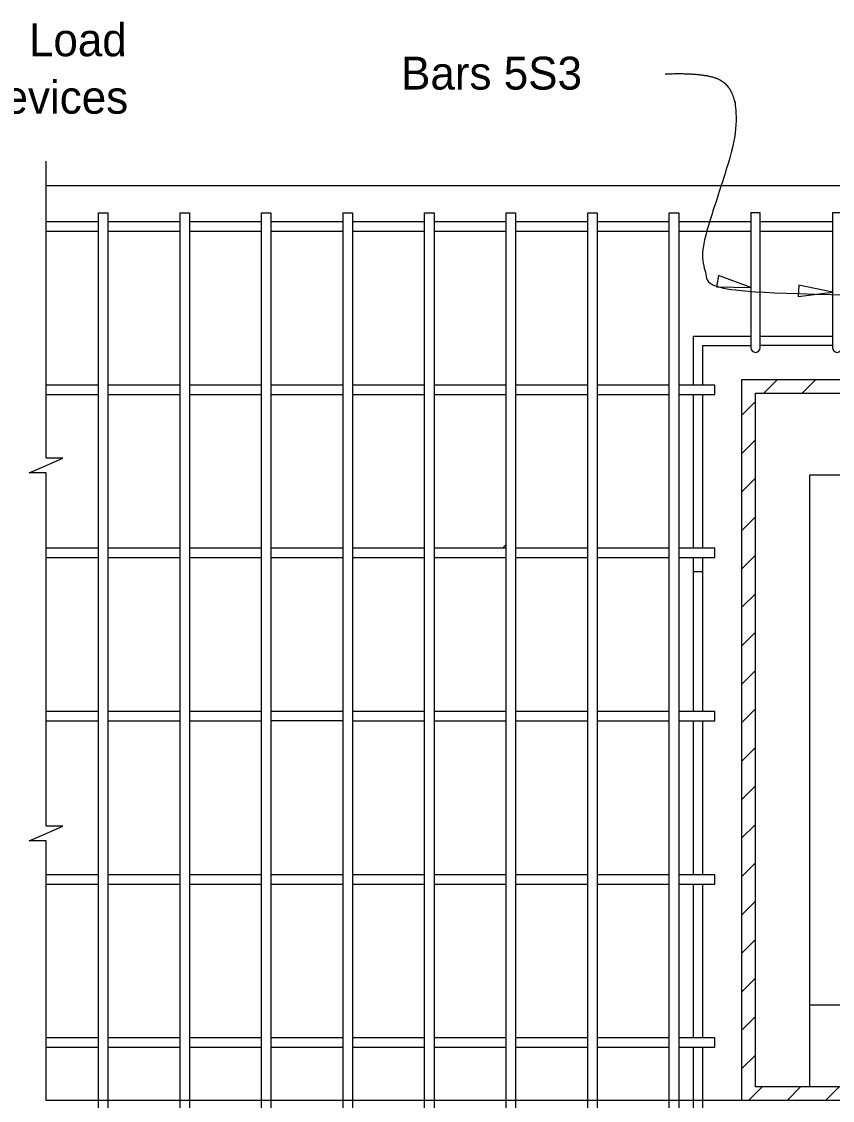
# Model space of a CAD drawing. Extents: x 120577.8 to 120649.9, y 120677.2 to 120721.6.
# Drawn here: x 120598.08 to 120603.05, y 120708.42 to 120715.03 of the extents above; entities that cross this region are included whole.
import ezdxf

# ---------------------------------------------------------------- set-up
doc = ezdxf.new("R2010")
doc.units = 0
for name, color, linetype in [('AdhocPoint_dp', 7, 'Continuous'), ('Border', 7, 'Continuous'), ('Patterning', 7, 'Continuous'), ('PlotBorder_dp', 7, 'Continuous'), ('TextMisc', 7, 'Continuous')]:
    doc.layers.add(name, color=color, linetype=linetype)

msp = doc.modelspace()

# ---------------------------------------------------------------- linework, layer by layer
at = {"layer": 'Border'}
for p, q in [((120602.6314, 120712.7572), (120602.7147, 120712.8405)), ((120602.867, 120712.7572), (120602.9503, 120712.8405)), ((120602.5808, 120708.5072), (120602.5808, 120712.7572)), ((120602.5808, 120712.7572), (120607.5808, 120712.7572)), ((120602.4975, 120712.6232), (120602.5808, 120712.7065)), ((120602.4975, 120712.3877), (120602.5808, 120712.471)), ((120602.4975, 120712.1521), (120602.5808, 120712.2354)), ((120602.9141, 120712.2572), (120607.2474, 120712.2572)), ((120602.9141, 120708.5072), (120602.9141, 120712.2572)), ((120602.4975, 120711.9166), (120602.5808, 120711.9999)), ((120602.4975, 120711.681), (120602.5808, 120711.7643)), ((120602.4975, 120711.4454), (120602.5808, 120711.5287)), ((120602.4975, 120711.2099), (120602.5808, 120711.2932)), ((120602.4975, 120710.9743), (120602.5808, 120711.0576)), ((120602.4975, 120710.7388), (120602.5808, 120710.8221)), ((120602.4975, 120710.5032), (120602.5808, 120710.5865)), ((120602.4975, 120710.2677), (120602.5808, 120710.351)), ((120602.4975, 120710.0321), (120602.5808, 120710.1154)), ((120602.4975, 120709.7966), (120602.5808, 120709.8799)), ((120602.4975, 120709.561), (120602.5808, 120709.6443)), ((120602.4975, 120709.3255), (120602.5808, 120709.4088)), ((120602.4975, 120709.0899), (120602.5808, 120709.1732)), ((120607.2474, 120709.0072), (120602.9141, 120709.0072)), ((120602.4975, 120708.8543), (120602.5808, 120708.9376)), ((120602.4975, 120708.6188), (120602.5808, 120708.7021)), ((120602.5381, 120708.4239), (120602.6214, 120708.5072)), ((120607.5808, 120708.5072), (120602.5808, 120708.5072)), ((120602.7736, 120708.4239), (120602.8569, 120708.5072)), ((120603.0092, 120708.4239), (120603.0925, 120708.5072))]:
    msp.add_line(p, q, dxfattribs=at)
at = {"layer": 'Patterning'}
for p, q in [((120598.5521, 120707.2437), (120598.5521, 120713.8614)), ((120598.5521, 120713.8614), (120598.6094, 120713.8614)), ((120598.6094, 120713.8614), (120598.6094, 120707.9744)), ((120599.0521, 120707.2437), (120599.0521, 120713.8614)), ((120599.0521, 120713.8614), (120599.1094, 120713.8614)), ((120599.1094, 120713.8614), (120599.1094, 120707.9744)), ((120599.5521, 120707.2437), (120599.5521, 120713.8614)), ((120599.5521, 120713.8614), (120599.6094, 120713.8614)), ((120599.6094, 120713.8614), (120599.6094, 120707.9744)), ((120600.0521, 120707.2437), (120600.0521, 120713.8614)), ((120600.0521, 120713.8614), (120600.1094, 120713.8614)), ((120600.1094, 120713.8614), (120600.1094, 120707.9744)), ((120600.5521, 120707.2437), (120600.5521, 120713.8614)), ((120600.5521, 120713.8614), (120600.6094, 120713.8614)), ((120600.6094, 120713.8614), (120600.6094, 120707.9744)), ((120601.0521, 120707.2437), (120601.0521, 120713.8614)), ((120601.0521, 120713.8614), (120601.1094, 120713.8614)), ((120601.1094, 120713.8614), (120601.1094, 120707.9744)), ((120601.5521, 120707.2437), (120601.5521, 120713.8614)), ((120601.5521, 120713.8614), (120601.6094, 120713.8614)), ((120601.6094, 120713.8614), (120601.6094, 120707.9744)), ((120602.0521, 120707.2437), (120602.0521, 120713.8614)), ((120602.0521, 120713.8614), (120602.1094, 120713.8614)), ((120602.1094, 120713.8614), (120602.1094, 120707.9744)), ((120602.6094, 120713.8614), (120602.5521, 120713.8614)), ((120602.5521, 120713.8614), (120602.5521, 120713.0358)), ((120602.6094, 120713.0358), (120602.6094, 120713.8614)), ((120603.1094, 120713.8614), (120603.0521, 120713.8614)), ((120603.0521, 120713.8614), (120603.0521, 120713.0358)), ((120602.1974, 120713.1061), (120602.1974, 120712.8067)), ((120602.2547, 120713.0488), (120602.5521, 120713.0488)), ((120602.2547, 120713.0488), (120602.2547, 120712.8067)), ((120602.3308, 120712.7494), (120602.3308, 120712.8067)), ((120602.1974, 120712.7494), (120602.1974, 120711.8067)), ((120602.2547, 120712.7494), (120602.2547, 120711.8067)), ((120601.029, 120711.8067), (120601.0521, 120711.8298)), ((120602.3308, 120711.7494), (120602.3308, 120711.8067)), ((120602.1974, 120711.7494), (120602.1974, 120710.8067)), ((120602.2547, 120711.7494), (120602.2547, 120710.8067)), ((120602.1974, 120711.6655), (120602.2547, 120711.6655)), ((120602.1974, 120710.7494), (120602.1974, 120709.8067)), ((120602.2547, 120710.7494), (120602.2547, 120709.8067)), ((120602.3308, 120710.7494), (120602.3308, 120710.8067)), ((120602.3308, 120709.7494), (120602.3308, 120709.8067)), ((120602.1974, 120709.7494), (120602.1974, 120708.8067)), ((120602.2547, 120709.7494), (120602.2547, 120708.8067)), ((120602.3308, 120708.7494), (120602.3308, 120708.8067)), ((120602.1974, 120708.7494), (120602.1974, 120708.1426)), ((120602.2547, 120708.7494), (120602.2547, 120708.1999))]:
    msp.add_line(p, q, dxfattribs=at)
for points in [[(120598.5521, 120713.8067), (120598.2308, 120713.8067)], [(120599.0521, 120713.8067), (120598.6094, 120713.8067)], [(120599.5521, 120713.8067), (120599.1094, 120713.8067)], [(120600.0521, 120713.8067), (120599.6094, 120713.8067)], [(120600.5521, 120713.8067), (120600.1094, 120713.8067)], [(120601.0521, 120713.8067), (120600.6094, 120713.8067)], [(120601.5521, 120713.8067), (120601.1094, 120713.8067)], [(120602.0521, 120713.8067), (120601.6094, 120713.8067)], [(120602.5521, 120713.8067), (120602.1094, 120713.8067)], [(120603.0521, 120713.8067), (120602.6094, 120713.8067)], [(120598.2308, 120713.7494), (120598.5521, 120713.7494)], [(120598.6094, 120713.7494), (120599.0521, 120713.7494)], [(120599.1094, 120713.7494), (120599.5521, 120713.7494)], [(120599.6094, 120713.7494), (120600.0521, 120713.7494)], [(120600.1094, 120713.7494), (120600.5521, 120713.7494)], [(120600.6094, 120713.7494), (120601.0521, 120713.7494)], [(120601.1094, 120713.7494), (120601.5521, 120713.7494)], [(120601.6094, 120713.7494), (120602.0521, 120713.7494)], [(120602.1094, 120713.7494), (120602.5521, 120713.7494)], [(120602.6094, 120713.7494), (120603.0521, 120713.7494)], [(120602.1974, 120713.1061), (120602.5521, 120713.1061)], [(120602.6094, 120713.1061), (120603.0521, 120713.1061)], [(120603.0521, 120713.0488), (120602.6094, 120713.0488)], [(120598.5521, 120712.8067), (120598.2308, 120712.8067)], [(120599.0521, 120712.8067), (120598.6094, 120712.8067)], [(120599.5521, 120712.8067), (120599.1094, 120712.8067)], [(120600.0521, 120712.8067), (120599.6094, 120712.8067)], [(120600.5521, 120712.8067), (120600.1094, 120712.8067)], [(120601.0521, 120712.8067), (120600.6094, 120712.8067)], [(120601.5521, 120712.8067), (120601.1094, 120712.8067)], [(120602.0521, 120712.8067), (120601.6094, 120712.8067)], [(120602.3308, 120712.8067), (120602.1094, 120712.8067)], [(120598.2308, 120712.7494), (120598.5521, 120712.7494)], [(120598.6094, 120712.7494), (120599.0521, 120712.7494)], [(120599.1094, 120712.7494), (120599.5521, 120712.7494)], [(120599.6094, 120712.7494), (120600.0521, 120712.7494)], [(120600.1094, 120712.7494), (120600.5521, 120712.7494)], [(120600.6094, 120712.7494), (120601.0521, 120712.7494)], [(120601.1094, 120712.7494), (120601.5521, 120712.7494)], [(120601.6094, 120712.7494), (120602.0521, 120712.7494)], [(120602.1094, 120712.7494), (120602.3308, 120712.7494)], [(120598.5521, 120711.8067), (120598.2308, 120711.8067)], [(120599.0521, 120711.8067), (120598.6094, 120711.8067)], [(120599.5521, 120711.8067), (120599.1094, 120711.8067)], [(120600.0521, 120711.8067), (120599.6094, 120711.8067)], [(120600.5521, 120711.8067), (120600.1094, 120711.8067)], [(120601.0521, 120711.8067), (120600.6094, 120711.8067)], [(120601.5521, 120711.8067), (120601.1094, 120711.8067)], [(120602.0521, 120711.8067), (120601.6094, 120711.8067)], [(120602.3308, 120711.8067), (120602.1094, 120711.8067)], [(120598.2308, 120711.7494), (120598.5521, 120711.7494)], [(120598.6094, 120711.7494), (120599.0521, 120711.7494)], [(120599.1094, 120711.7494), (120599.5521, 120711.7494)], [(120599.6094, 120711.7494), (120600.0521, 120711.7494)], [(120600.1094, 120711.7494), (120600.5521, 120711.7494)], [(120600.6094, 120711.7494), (120601.0521, 120711.7494)], [(120601.1094, 120711.7494), (120601.5521, 120711.7494)], [(120601.6094, 120711.7494), (120602.0521, 120711.7494)], [(120602.1094, 120711.7494), (120602.3308, 120711.7494)], [(120598.5521, 120710.8067), (120598.2308, 120710.8067)], [(120598.2308, 120710.7494), (120598.5521, 120710.7494)], [(120599.0521, 120710.8067), (120598.6094, 120710.8067)], [(120598.6094, 120710.7494), (120599.0521, 120710.7494)], [(120599.5521, 120710.8067), (120599.1094, 120710.8067)], [(120599.1094, 120710.7494), (120599.5521, 120710.7494)], [(120600.0521, 120710.8067), (120599.6094, 120710.8067)], [(120600.0521, 120710.7494), (120599.6094, 120710.7494)], [(120600.5521, 120710.8067), (120600.1094, 120710.8067)], [(120600.1094, 120710.7494), (120600.5521, 120710.7494)], [(120601.0521, 120710.8067), (120600.6094, 120710.8067)], [(120600.6094, 120710.7494), (120601.0521, 120710.7494)], [(120601.5521, 120710.8067), (120601.1094, 120710.8067)], [(120601.1094, 120710.7494), (120601.5521, 120710.7494)], [(120602.0521, 120710.8067), (120601.6094, 120710.8067)], [(120601.6094, 120710.7494), (120602.0521, 120710.7494)], [(120602.3308, 120710.8067), (120602.1094, 120710.8067)], [(120602.1094, 120710.7494), (120602.3308, 120710.7494)], [(120598.5521, 120709.8067), (120598.2308, 120709.8067)], [(120599.0521, 120709.8067), (120598.6094, 120709.8067)], [(120599.5521, 120709.8067), (120599.1094, 120709.8067)], [(120600.0521, 120709.8067), (120599.6094, 120709.8067)], [(120600.5521, 120709.8067), (120600.1094, 120709.8067)], [(120601.0521, 120709.8067), (120600.6094, 120709.8067)], [(120601.5521, 120709.8067), (120601.1094, 120709.8067)], [(120602.0521, 120709.8067), (120601.6094, 120709.8067)], [(120602.3308, 120709.8067), (120602.1094, 120709.8067)], [(120598.2308, 120709.7494), (120598.5521, 120709.7494)], [(120598.6094, 120709.7494), (120599.0521, 120709.7494)], [(120599.1094, 120709.7494), (120599.5521, 120709.7494)], [(120599.6094, 120709.7494), (120600.0521, 120709.7494)], [(120600.1094, 120709.7494), (120600.5521, 120709.7494)], [(120600.6094, 120709.7494), (120601.0521, 120709.7494)], [(120601.1094, 120709.7494), (120601.5521, 120709.7494)], [(120601.6094, 120709.7494), (120602.0521, 120709.7494)], [(120602.1094, 120709.7494), (120602.3308, 120709.7494)], [(120598.5521, 120708.8067), (120598.2308, 120708.8067)], [(120599.0521, 120708.8067), (120598.6094, 120708.8067)], [(120599.5521, 120708.8067), (120599.1094, 120708.8067)], [(120600.0521, 120708.8067), (120599.6094, 120708.8067)], [(120600.5521, 120708.8067), (120600.1094, 120708.8067)], [(120601.0521, 120708.8067), (120600.6094, 120708.8067)], [(120601.5521, 120708.8067), (120601.1094, 120708.8067)], [(120602.0521, 120708.8067), (120601.6094, 120708.8067)], [(120602.3308, 120708.8067), (120602.1094, 120708.8067)], [(120598.2308, 120708.7494), (120598.5521, 120708.7494)], [(120598.6094, 120708.7494), (120599.0521, 120708.7494)], [(120599.1094, 120708.7494), (120599.5521, 120708.7494)], [(120599.6094, 120708.7494), (120600.0521, 120708.7494)], [(120600.1094, 120708.7494), (120600.5521, 120708.7494)], [(120600.6094, 120708.7494), (120601.0521, 120708.7494)], [(120601.1094, 120708.7494), (120601.5521, 120708.7494)], [(120601.6094, 120708.7494), (120602.0521, 120708.7494)], [(120602.1094, 120708.7494), (120602.3308, 120708.7494)]]:
    msp.add_lwpolyline(points, dxfattribs=at)
for centre in [(120602.5808, 120713.0358), (120603.0808, 120713.0358)]:
    msp.add_arc(centre, 0.0286, 180, 0, dxfattribs=at)
at = {"layer": 'PlotBorder_dp'}
for points in [[(120598.2307, 120710.7494), (120598.2307, 120712.2689), (120598.1274, 120712.2689), (120598.2307, 120712.3139), (120598.3341, 120712.3589), (120598.2307, 120712.3589), (120598.2307, 120714.178)], [(120598.2307, 120708.4239), (120598.2307, 120710.0138), (120598.1274, 120710.0138), (120598.2307, 120710.0588), (120598.3341, 120710.1038), (120598.2307, 120710.1038), (120598.2307, 120710.7494)]]:
    msp.add_lwpolyline(points, dxfattribs=at)
for points in [[(120602.5521, 120713.4036), (120602.3545, 120713.4782), (120602.3409, 120713.4089)], [(120603.0521, 120713.3761), (120602.8453, 120713.4193), (120602.8426, 120713.3487)]]:
    msp.add_lwpolyline(points, close=True, dxfattribs=at)
msp.add_open_spline([(120602.0274, 120714.7135), (120602.3163, 120714.7241), (120602.4593, 120714.5968), (120602.4673, 120714.3157), (120602.2527, 120713.6845), (120602.2527, 120713.4511), (120602.56, 120713.3344), (120607.5521, 120713.3556)], degree=2, dxfattribs=at)
at = {"layer": 'TextMisc'}
for p, q in [((120611.9308, 120714.028), (120598.2308, 120714.028)), ((120602.4975, 120712.8405), (120607.6641, 120712.8405)), ((120602.4975, 120708.4238), (120602.4975, 120712.8405)), ((120611.2601, 120708.4238), (120598.2308, 120708.4238))]:
    msp.add_line(p, q, dxfattribs=at)

# ---------------------------------------------------------------- texts
at = {"layer": 'AdhocPoint_dp'}
msp.add_text('Bars 5S3', height=0.2016, dxfattribs=at).set_placement((120600.4077, 120714.6173))
at = {"layer": 'PlotBorder_dp'}
for s, p in [('1" Ø Dowel Load ', (120596.697, 120714.8216)), ('Transfer Devices ', (120596.697, 120714.4696))]:
    msp.add_text(s, height=0.2016, dxfattribs=at).set_placement(p)

doc.saveas('drawing.dxf')
